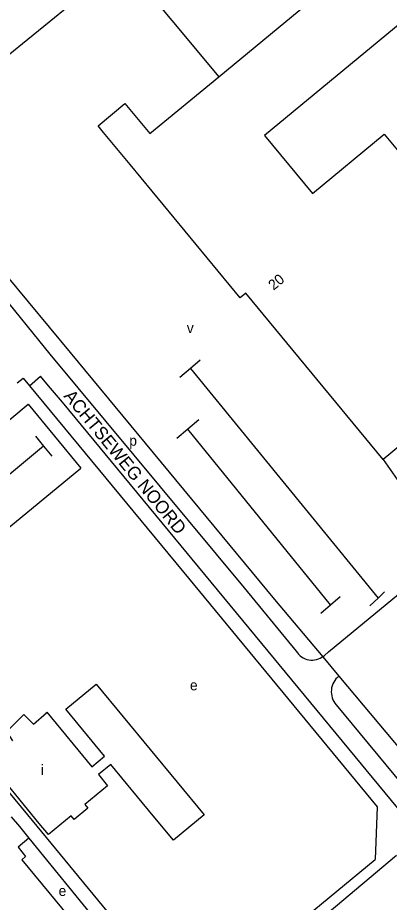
# Model space of a CAD drawing. Extents: x 156097 to 158136, y 385644 to 388348.
# Drawn here: x 157303.6 to 157447.6, y 386635.8 to 386978.7 of the extents above; entities that cross this region are included whole.
import ezdxf

# ---------------------------------------------------------------- set-up
doc = ezdxf.new("R2010")
doc.units = 0
for name, color, linetype in [('BLT_Basislijn', 7, 'Continuous'), ('BLT_Bebouwing', 7, 'Continuous'), ('BLT_Centroide', 7, 'Continuous'), ('BLT_Huisnummer', 7, 'Continuous'), ('BLT_Straatnaam', 7, 'Continuous')]:
    doc.layers.add(name, color=color, linetype=linetype)

msp = doc.modelspace()

# ---------------------------------------------------------------- linework, layer by layer
at = {"layer": 'BLT_Basislijn'}
for p, q in [((157335.94, 386993.39), (157292.12, 386957.75)), ((157283.2, 386888.8), (157315.99, 386848.3)), ((157315.99, 386848.3), (157391.33, 386757.69)), ((157323.88, 386848.91), (157403.07, 386753.23)), ((157374.37, 386845.93), (157370.55, 386842.7)), ((157370.55, 386842.7), (157366.48, 386839.24)), ((157370.55, 386842.7), (157443.26, 386753.74)), ((157303.44, 386837.13), (157305.73, 386839.01)), ((157305.73, 386839.01), (157308.16, 386836.05)), ((157308.16, 386836.05), (157312.48, 386839.79)), ((157315.57, 386836.04), (157312.48, 386839.79)), ((157308.16, 386836.05), (157367.3, 386764.45)), ((157268.95, 386796.97), (157307.63, 386828.85)), ((157307.63, 386828.85), (157328.03, 386804.15)), ((157373.76, 386822.84), (157369.51, 386819.19)), ((157310.47, 386816.47), (157313.65, 386812.61)), ((157369.51, 386819.19), (157365.26, 386815.55)), ((157424.83, 386751.11), (157369.51, 386819.19)), ((157313.65, 386812.61), (157279.03, 386784.08)), ((157313.65, 386812.61), (157316.83, 386808.75)), ((157284.55, 386768.31), (157328.03, 386804.15)), ((157424.12, 386732.9), (157470.54, 386771.33)), ((157391.33, 386757.69), (157411.57, 386733.14)), ((157424.83, 386751.11), (157428.62, 386754.39)), ((157443.26, 386753.74), (157445.82, 386756.21)), ((157403.07, 386753.23), (157421.83, 386731)), ((157421.13, 386747.91), (157424.83, 386751.11)), ((157440.15, 386750.74), (157443.26, 386753.74)), ((157421.83, 386731), (157428.09, 386723.52)), ((157422.5, 386731.52), (157424.12, 386732.9)), ((157427.08, 386712.38), (157509.23, 386612.72)), ((157285.21, 386696.53), (157307.37, 386669.67)), ((157442.93, 386672.87), (157442.13, 386652.35)), ((157307.37, 386669.67), (157327.25, 386645.55)), ((157307.93, 386660.66), (157351.23, 386607.69)), ((157400.13, 386617.86), (157442.13, 386652.35))]:
    msp.add_line(p, q, dxfattribs=at)
for points in [[(157345.15, 386999.62), (157381.52, 386955.83)], [(157291.3, 386888.19), (157323.88, 386848.91)], [(157453.42, 386669.32), (157320.9, 386829.73), (157315.57, 386836.04)], [(157445.3, 386807.51), (157470.54, 386771.33)], [(157367.3, 386764.45), (157442.93, 386672.87)], [(157411.57, 386733.14), (157412, 386732.52), (157412.49, 386731.94), (157413.05, 386731.42), (157413.65, 386730.96), (157414.3, 386730.56), (157414.98, 386730.24), (157415.7, 386729.99), (157416.44, 386729.82), (157417.19, 386729.72), (157417.95, 386729.7), (157418.7, 386729.77), (157419.45, 386729.91), (157420.18, 386730.13), (157420.87, 386730.43), (157421.54, 386730.8), (157421.83, 386731)], [(157421.83, 386731), (157422.16, 386731.23), (157422.5, 386731.52)], [(157428.09, 386723.52), (157427.5, 386723.01), (157426.96, 386722.44), (157426.49, 386721.82), (157426.08, 386721.15), (157425.74, 386720.45), (157425.47, 386719.71), (157425.28, 386718.95), (157425.17, 386718.18), (157425.14, 386717.4), (157425.19, 386716.61), (157425.32, 386715.84), (157425.52, 386715.09), (157425.8, 386714.36), (157426.16, 386713.66), (157426.58, 386713), (157427.08, 386712.38)], [(157428.09, 386723.52), (157516.44, 386618.21)], [(157383.79, 386598.53), (157413.76, 386623.26), (157450.46, 386654.06)], [(157327.25, 386645.55), (157364.09, 386600.85)]]:
    msp.add_lwpolyline(points, dxfattribs=at)
at = {"layer": 'BLT_Bebouwing'}
msp.add_line((157336.87, 386934.27), (157334.74, 386936.85), dxfattribs=at)
for points in [[(157381.52, 386955.83), (157483.87, 387040.42), (157502.2, 387018.23), (157399.23, 386933.1), (157417.83, 386910.59), (157445.69, 386933.62), (157454.08, 386923.48), (157587.31, 387033.54), (157640.68, 386968.97), (157445.3, 386807.51)], [(157334.74, 386936.85), (157345.13, 386945.47), (157354.84, 386933.77), (157381.52, 386955.83)], [(157347.15, 386921.82), (157336.87, 386934.27)], [(157445.3, 386807.51), (157392, 386871.98), (157389.82, 386870.18), (157347.15, 386921.82)], [(157322.21, 386710.63), (157334.05, 386720.37), (157375.83, 386669.68), (157363.93, 386659.88)], [(157337.21, 386692.4), (157322.21, 386710.63)], [(157301.75, 386698.38), (157299.33, 386702.03), (157305.99, 386708.58)], [(157305.99, 386708.58), (157309.66, 386704.85), (157314.81, 386709.21), (157314.68, 386709.38), (157314.94, 386709.58)], [(157314.94, 386709.58), (157332.38, 386688.37), (157337.21, 386692.4)], [(157311.95, 386666.4), (157292, 386690.67)], [(157339.71, 386689.29), (157334.87, 386685.3), (157338.42, 386680.99), (157329.61, 386673.74), (157330.77, 386672.33), (157325.45, 386667.97), (157324.27, 386669.34), (157315.5, 386662.09), (157311.95, 386666.4)], [(157356.13, 386669.36), (157339.71, 386689.29)], [(157301.08, 386668.97), (157304.24, 386665.14)], [(157363.93, 386659.88), (157356.13, 386669.36)], [(157304.24, 386665.14), (157306.87, 386661.94), (157307.93, 386660.66)], [(157307.93, 386660.66), (157303.74, 386657.16)], [(157303.74, 386657.16), (157306.66, 386653.54)], [(157306.66, 386653.54), (157305.19, 386652.34), (157328.57, 386623.97), (157330.05, 386625.19)]]:
    msp.add_lwpolyline(points, dxfattribs=at)

# ---------------------------------------------------------------- texts
at = {"layer": 'BLT_Centroide'}
for s, p in [('v', (157369.14, 386856.47)), ('p', (157346.84, 386812.8)), ('e', (157370.36, 386717.99)), ('i', (157312.56, 386685.19)), ('e', (157319.45, 386638.28))]:
    msp.add_text(s, height=4, dxfattribs=at).set_placement(p)
at = {"layer": 'BLT_Huisnummer'}
msp.add_text('20', height=4, rotation=39.4949, dxfattribs=at).set_placement((157402.77, 386872.87))
at = {"layer": 'BLT_Straatnaam'}
msp.add_text('ACHTSEWEG NOORD', height=5, rotation=309.3973, dxfattribs=at).set_placement((157321.17, 386831.94))

doc.saveas('drawing.dxf')
